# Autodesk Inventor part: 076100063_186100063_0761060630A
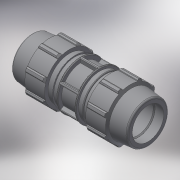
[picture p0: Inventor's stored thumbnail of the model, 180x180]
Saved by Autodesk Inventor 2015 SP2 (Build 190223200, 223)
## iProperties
Created: 2017-02
Part Number: 076100063_186100063_0761060630A
Material: Generic
Description: PLASSON REPAIR COUPLER 63
Document SubType Name: Modeling
Designer: KIM
Mass: 1143.55 g
Surface Area: 1691.95 cm^2
Volume: 1143.55 cm^3
Density: 1 g/cm^3
Appearance: Default
Author: KIM
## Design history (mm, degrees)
derived "07610.ipt"
feature "Solid1::07610.ipt"
tag "TaggingFeature1"
body "Solid1"
other parameters: "d2" = 63, "d4" = 22.5, "d5" = 38.57143, "d7" = 113, "d8" = 84.75, "d9" = 38.57143, "d11" = 3.48571, "d12" = 90.4, "d13" = 120 deg, "d14" = 88.2, "d15" = 6 deg, "d16" = 101.7, "d18" = 3.15, "d19" = 35 deg, "d20" = 17.5 deg, "d21" = 105.09, "d23" = 0, "d25" = 360 deg, "d27" = 2.26, "d33" = 1.26, "d34" = 5.65, "d36" = 0, "d37" = 1.26, "d38" = 1.26, "d40" = 360 deg, "d42" = 48.6, "d43" = 3.39, "d46" = 1.89, "d50" = 10.6, "d51" = 90.4, "d_" = 63, "E_" = 113, "d49" = 24.68571
